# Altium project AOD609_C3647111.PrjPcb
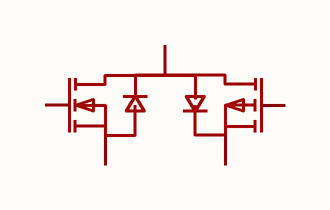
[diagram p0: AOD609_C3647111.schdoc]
1 sheet, 1 parts. Net scope: global (net labels, ports and power ports of the same name join across sheets).

## Sheet AOD609_C3647111.schdoc
size 127 x 101 mm

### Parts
Q?  aod609-ms  [TO-252-4_L6.6-W6.1-P1.27-LS10-TL]  (value not drawn)

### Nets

Not connected (* = marked no-connect by the designer): Q? 1(S) 2(G) 3(D) 4(S) 5(G)

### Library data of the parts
Q? = aod609-ms: 数量:1个N沟道+1个P沟道;漏源电压(Vdss):40V;连续漏极电流(Id):30A;导通电阻(RDS(on)):30mΩ@10V;耗散功率(Pd):30W;阈值电压(Vgs(th)):2.5V;; Manufacturer: MSKSEMI(美森科); Symbol: AOD609_C3647111; AddInBom: yes; ModelId: 8151d6e4b177452b8925147fa9fba861; ModelTransform: 259.99948,389.763,0,270,0,0,28.464,-0.001,0; Drain to Source Voltage: 40V; Current - Continuous Drain(Id): 30A; Pd - Power Dissipation: 30W; Gate Threshold Voltage (Vgs(th)): 2.5V; Gate Charge(Qg): 5.2nC@4.5V; Input Capacitance(Ciss): 420pF; Reverse Transfer Capacitance (Crss@Vds): 40pF; Configuration: 半桥；全桥; Type: N沟道+P沟道; Output Capacitance(Coss): 65pF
